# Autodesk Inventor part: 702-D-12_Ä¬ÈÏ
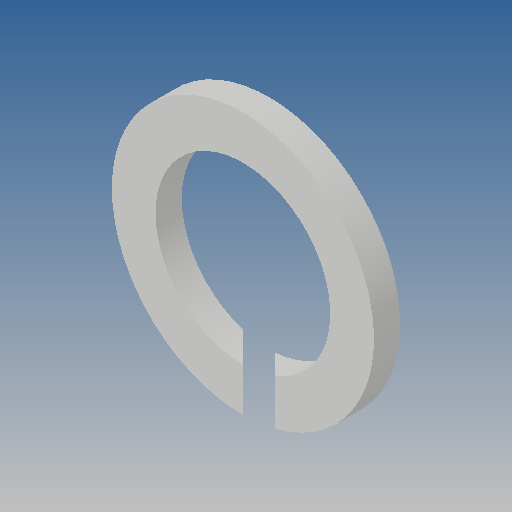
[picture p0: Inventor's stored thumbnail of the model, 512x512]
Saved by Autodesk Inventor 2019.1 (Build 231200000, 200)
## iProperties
Created: 2010-06
Part Number: 702-D-12_Ä¬ÈÏ
Material: Ogólny
Document SubType Name: Modeling
Designer: CADENGINEERING4
Density: 1 g/cm^3
Appearance: Domyślna
Author: CADENGINEERING4
Revision Number: ÈÎºÎ
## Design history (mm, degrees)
feature "NONE"
node "Bryła1"
